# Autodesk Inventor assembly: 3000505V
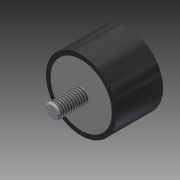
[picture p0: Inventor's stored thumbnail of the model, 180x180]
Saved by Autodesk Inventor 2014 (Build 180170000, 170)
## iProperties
Company: NHTSA/VRTC
Created: 2012-12
Project: CHILD SIDE IMPACT SLED
Catalog Web Link: www.mcmaster.com
Description: RUBBER BUMPER - %%c1 1/2" x 1" HT. - 5/16-18 THREADS x 5/8" LONG
Vendor: McMaster-Carr
Document SubType Name: Assembly
Designer: Dave Walker
Stock Number: 8926T27
Part Number: 3000505V
Title: Bumper
Subject: Child Side Impact Sled
Author: Dave Walker
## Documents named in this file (3)
- B:\VRTC_DWG\BIO\Non-P572\Child Side-Frontal Impact Sled\Side Impact Sled\Bumper.iam
- B:\VRTC_DWG\BIO\Non-P572\Child Side-Frontal Impact Sled\Side Impact Sled\Bumper - Rubber.ipt
- B:\VRTC_DWG\BIO\Non-P572\Child Side-Frontal Impact Sled\Side Impact Sled\Bumper - Steel Insert.ipt
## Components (2 placed, 2 different names)
1. Bumper - Rubber:1 — Insert:1
2. Bumper - Steel Insert:1 — Insert:1
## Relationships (1: Insert 1)
- Insert:1: Bumper - Rubber:1 ↔ Bumper - Steel Insert:1
